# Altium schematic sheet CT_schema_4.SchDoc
size 316 x 200 mm
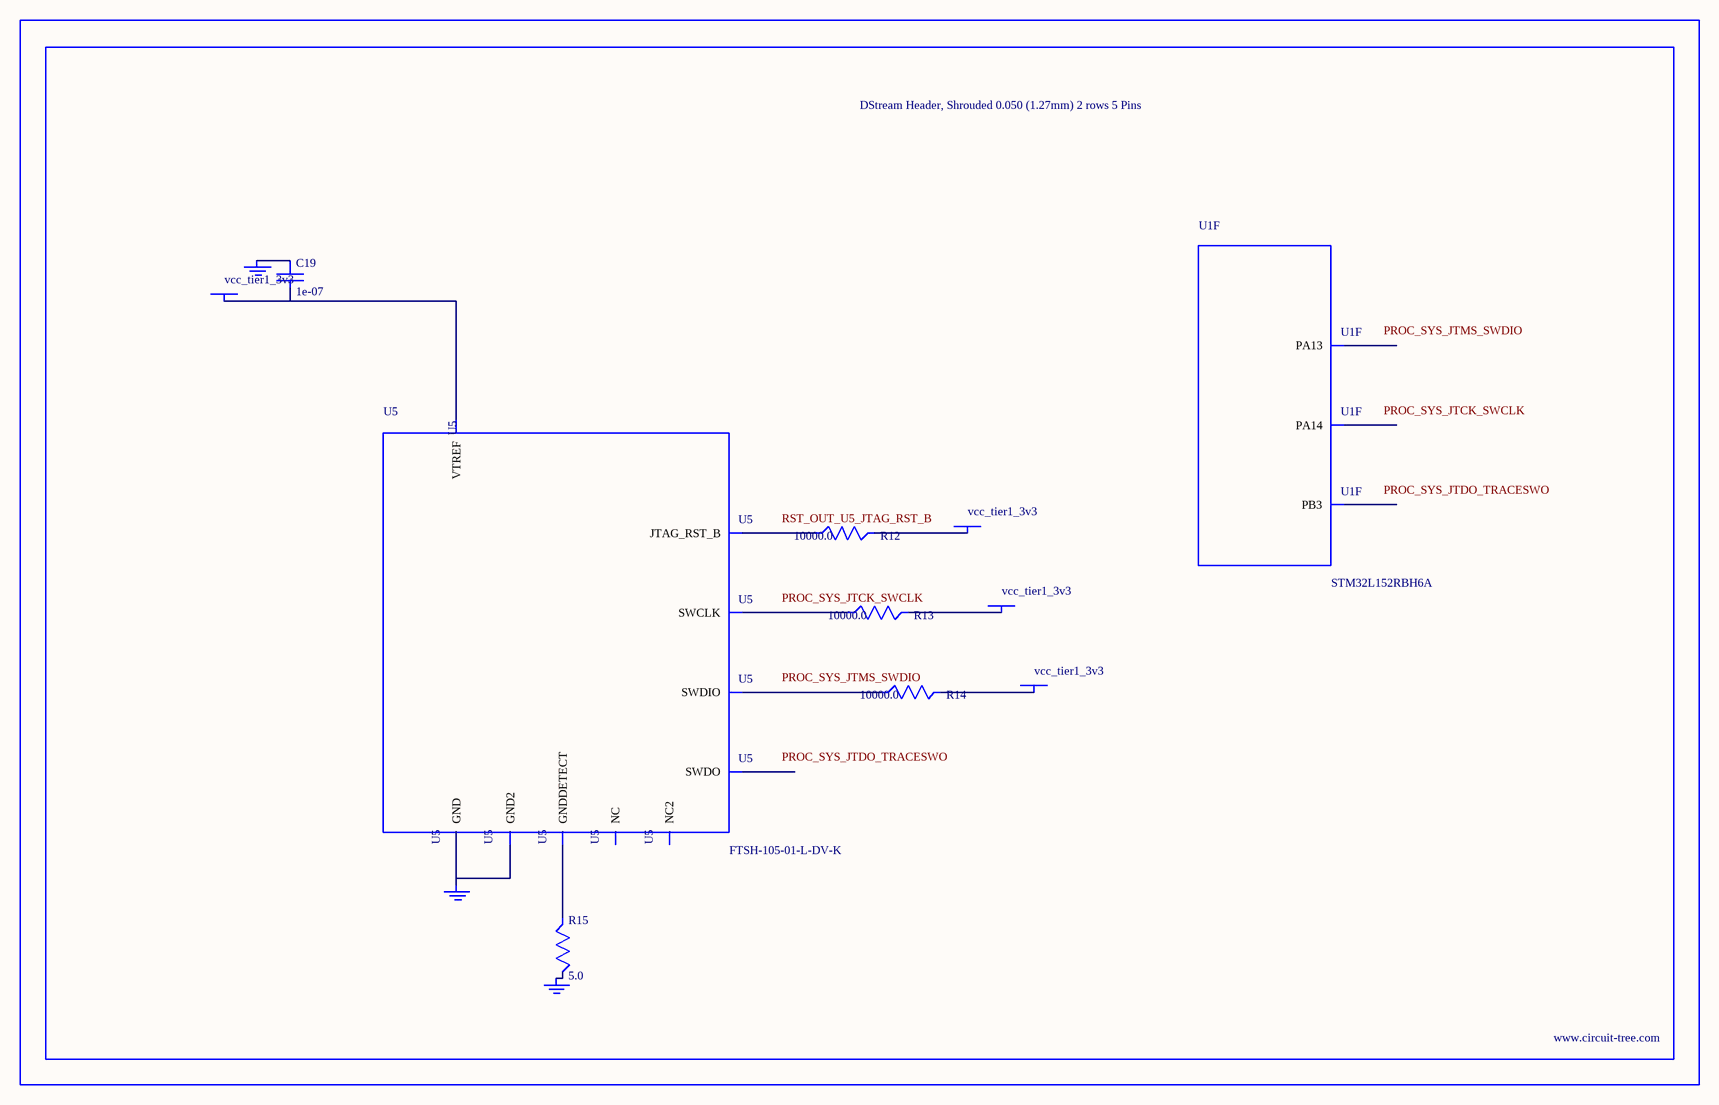
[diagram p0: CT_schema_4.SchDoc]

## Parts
BORDER3  (no value)
C19  1e-07  [C0402]
GND_INSTANCE_3_0  (no value)
GND_INSTANCE_3_1  (no value)
GND_INSTANCE_3_2  (no value)
POWER_INSTANCE_3_0  vcc_tier1_3v3
POWER_INSTANCE_3_1  vcc_tier1_3v3
POWER_INSTANCE_3_2  vcc_tier1_3v3
POWER_INSTANCE_3_3  vcc_tier1_3v3
R12  10000.0  [R0603]
R13  10000.0  [R0603]
R14  10000.0  [R0603]
R15  5.0  [R0603]
U1  STM32L152RBH6A  [TFBGA64]  (part F of 7)
U5  FTSH-105-01-L-DV-K  [SAMTEC_FTSH-105-01-L-DV-K]

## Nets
NetC19_1: C19.1 GND_INSTANCE_3_0.0(GND)
NetC19_2: C19.2 POWER_INSTANCE_3_0.0(PWR) U5.1(VTREF)
NetGND_INSTANCE_3_1_0: GND_INSTANCE_3_1.0(GND) R15.2
NetGND_INSTANCE_3_2_0: GND_INSTANCE_3_2.0(GND) U5.3(GND) U5.5(GND2)
NetPOWER_INSTANCE_3_1_0: POWER_INSTANCE_3_1.0(PWR) R14.2
NetPOWER_INSTANCE_3_2_0: POWER_INSTANCE_3_2.0(PWR) R13.2
NetPOWER_INSTANCE_3_3_0: POWER_INSTANCE_3_3.0(PWR) R12.2
NetR12_1: R12.1 U5.10(JTAG_RST_B)
NetR13_1: R13.1 U5.4(SWCLK)
NetR14_1: R14.1 U5.2(SWDIO)
NetR15_1: R15.1 U5.9(GNDDETECT)

Not connected (* = marked no-connect by the designer): U1 A5(PB3) A7(PA14) A8(PA13); U5 6(SWDO) 7(NC) 8(NC2)

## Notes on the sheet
- Labels drawn without touching a wire or pin: PROC_SYS_JTCK_SWCLK, PROC_SYS_JTDO_TRACESWO, PROC_SYS_JTMS_SWDIO, RST_OUT_U5_JTAG_RST_B

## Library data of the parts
BORDER3 = BORDER_PAGE3
C19 = C0402C104K3RACTU
GND_INSTANCE_3_0-GND_INSTANCE_3_2 = GND
POWER_INSTANCE_3_0-POWER_INSTANCE_3_3 = PWR
R12-R14 = RC0603JR-0710KL
R15 = ERJ-3GEYJ5R1V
